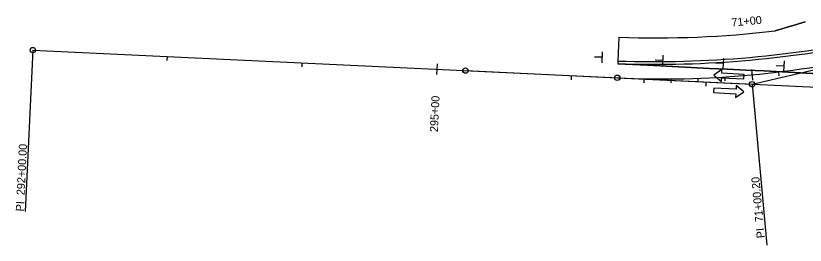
# Model space of a CAD drawing. Extents: x 1140339 to 1165793, y 1646213 to 1669071.
# Drawn here: x 1164080 to 1164666, y 1656639 to 1656809 of the extents above; entities that cross this region are included whole.
import ezdxf

# ---------------------------------------------------------------- set-up
doc = ezdxf.new("R2010")
doc.units = 0
for name, color, linetype in [('R_Horz Alg', 7, 'Continuous'), ('R_Horz Alg Annot', 7, 'Continuous'), ('R_MOT', 7, 'Continuous'), ('R_No Plot', 7, 'Continuous'), ('R_Proposed Const Limits_Fill', 7, 'Continuous'), ('R_Proposed Road_Lane', 7, 'Continuous'), ('R_Proposed Road_Shoulder', 7, 'Continuous')]:
    doc.layers.add(name, color=color, linetype=linetype)

msp = doc.modelspace()

# ---------------------------------------------------------------- linework, layer by layer
at = {"layer": 'R_Horz Alg'}
for p, q in [((1164092.75, 1656783.95), (1165790.84, 1656703.38)), ((1164413.61, 1656768.73), (1164526.15, 1656763.39))]:
    msp.add_line(p, q, dxfattribs=at)
msp.add_arc((1164560.09, 1657478.78), 716.2, 267.28333, 283.21228, dxfattribs=at)
at = {"layer": 'R_Horz Alg Annot'}
for p, q in [((1164626.23, 1656758.64), (1164723.78, 1656781.54)), ((1164526.15, 1656763.39), (1164626.23, 1656758.64))]:
    msp.add_line(p, q, dxfattribs=at)
for points in [[(1164092.75, 1656783.95), (1164087.06, 1656664.09)], [(1164192.49, 1656776.21), (1164192.63, 1656779.21)], [(1164292.38, 1656771.47), (1164292.52, 1656774.47)], [(1164392.6, 1656773.73), (1164392.22, 1656765.74)], [(1164492.15, 1656762), (1164492.3, 1656764.99)], [(1164625.67, 1656769.61), (1164626.41, 1656761.64)], [(1164646.29, 1656764.76), (1164645.93, 1656767.74)], [(1164546.07, 1656759.72), (1164546.13, 1656762.72)], [(1164566.16, 1656759.61), (1164566.13, 1656762.61)], [(1164586.24, 1656760.06), (1164586.13, 1656763.05)], [(1164592.04, 1656757.26), (1164592.18, 1656760.25)], [(1164606.29, 1656761.07), (1164606.1, 1656764.06)], [(1164626.23, 1656758.64), (1164637.21, 1656639.14)]]:
    msp.add_lwpolyline(points, dxfattribs=at)
for centre in [(1164092.75, 1656783.95), (1164413.61, 1656768.73), (1164526.15, 1656763.39), (1164626.23, 1656758.64)]:
    msp.add_circle(centre, 2, dxfattribs=at)
at = {"layer": 'R_MOT'}
for p, q in [((1164515.04, 1656782.57), (1164514.71, 1656774.57)), ((1164514.76, 1656778.59), (1164509.3, 1656778.82)), ((1164559.71, 1656776.23), (1164554.25, 1656776.46)), ((1164559.99, 1656780.2), (1164559.66, 1656772.21)), ((1164604.91, 1656778.02), (1164604.58, 1656770.03)), ((1164604.63, 1656774.05), (1164599.17, 1656774.28)), ((1164649.6, 1656771.96), (1164644.15, 1656772.18)), ((1164649.88, 1656775.93), (1164649.55, 1656767.93))]:
    msp.add_line(p, q, dxfattribs=at)
for points in [[(1164603.85, 1656769.56), (1164597.81, 1656765.34), (1164603.43, 1656760.57), (1164603.56, 1656763.37), (1164620.09, 1656762.59), (1164620.25, 1656765.96), (1164603.72, 1656766.75)], [(1164614, 1656748.8), (1164620.05, 1656753.02), (1164614.43, 1656757.79), (1164614.29, 1656754.98), (1164597.76, 1656755.77), (1164597.6, 1656752.4), (1164614.13, 1656751.61)]]:
    msp.add_lwpolyline(points, close=True, dxfattribs=at)
at = {"layer": 'R_No Plot'}
for p, q in [((1164527.31, 1656793.46), (1164526.71, 1656775.85)), ((1164526.71, 1656775.85), (1164526.64, 1656773.85))]:
    msp.add_line(p, q, dxfattribs=at)
for points in [[(1164665.68, 1656805.05), (1164660.72, 1656803.55), (1164658.36, 1656802.76), (1164655.77, 1656801.95), (1164650.79, 1656800.44), (1164649.11, 1656799.94), (1164645.79, 1656798.99), (1164643.41, 1656798.2)], [(1164526.64, 1656773.85), (1164548.55, 1656772.67), (1164580.97, 1656770.94), (1164594.5, 1656770.34), (1164608.03, 1656769.75), (1164621.57, 1656769.15), (1164635.1, 1656768.56), (1164648.58, 1656767.85), (1164662.05, 1656767.15), (1164675.52, 1656766.44), (1164689, 1656765.74), (1164709.14, 1656764.95), (1164713.11, 1656764.79)]]:
    msp.add_lwpolyline(points, dxfattribs=at)
msp.add_arc((1164553.87, 1657567.66), 774.65, 268.03532, 276.63754, dxfattribs=at)
at = {"layer": 'R_Proposed Const Limits_Fill'}
msp.add_line((1164527.31, 1656793.46), (1164526.71, 1656775.85), dxfattribs=at)
msp.add_lwpolyline([(1164642.59, 1656798.1), (1164645.79, 1656798.99), (1164649.11, 1656799.94), (1164650.79, 1656800.44), (1164655.77, 1656801.95), (1164658.36, 1656802.76), (1164660.72, 1656803.55), (1164665.68, 1656805.05)], dxfattribs=at)
msp.add_arc((1164553.87, 1657567.66), 774.65, 268.03532, 276.63754, dxfattribs=at)
at = {"layer": 'R_Proposed Road_Lane'}
msp.add_lwpolyline([(1164713.11, 1656764.79), (1164709.14, 1656764.95), (1164689, 1656765.74), (1164675.52, 1656766.44), (1164662.05, 1656767.15), (1164648.58, 1656767.85), (1164635.1, 1656768.56), (1164621.57, 1656769.15), (1164608.03, 1656769.75), (1164594.5, 1656770.34), (1164580.97, 1656770.94), (1164548.55, 1656772.67), (1164526.64, 1656773.85)], dxfattribs=at)
msp.add_arc((1164553.87, 1657567.66), 794.27, 268.03532, 282.1838, dxfattribs=at)
at = {"layer": 'R_Proposed Road_Shoulder'}
msp.add_line((1164526.71, 1656775.85), (1164526.64, 1656773.85), dxfattribs=at)
msp.add_arc((1164553.87, 1657567.66), 792.27, 268.03532, 282.1838, dxfattribs=at)

# ---------------------------------------------------------------- texts
at = {"layer": 'R_Horz Alg Annot'}
for s, rotation, p in [('71+00', 5.28333, (1164611.18, 1656801.41)), ('295+00', 87.28333, (1164393.17, 1656722.98)), ('PI  292+00.00', 87.28333, (1164086.06, 1656664.13)), ('PI  71+00.20', 95.24781, (1164635.7, 1656644.62))]:
    msp.add_text(s, height=6, rotation=rotation, dxfattribs=at).set_placement(p)

doc.saveas('drawing.dxf')
